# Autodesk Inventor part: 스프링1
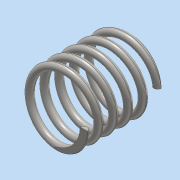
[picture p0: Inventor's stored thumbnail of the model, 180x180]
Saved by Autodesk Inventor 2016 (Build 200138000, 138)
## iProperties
Created: 2019-11
Part Number: 스프링1
Material: 스테인레스 스틸
Document SubType Name: Modeling
Designer: user
Density: 8 g/cm^3
Appearance: 반연마
Mass: 6.56989 g
Surface Area: 16.7192 cm^2
Volume: 0.821237 cm^3
Author: user
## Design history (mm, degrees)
sketch "스케치1"
  geometry: L1 (0, 0)-(8.5, 0); L2 (8.5, 0)-(8.5, -20.5); L3 (8.5, -20.5)-(0, -20.5); L4 (0, -20.5)-(0, 0); C1 r 1 at (8.5, 0)
  constraints: 8 end point, 2 parallel, 1 centre point, 1 coincident, 1 horizontal, 1 perpendicular
  dimensions: "d0" = 17 diameter of L2 L4; "d1" = 20.5 distance between parallel lines of L1 L3 (derived); "d2" = 2 diameter of C1
feature "코일1" sketch "스케치1" pitch "d3" = 10; turns "d5" = 5; dims "d4" = 20.5 (= d1), "d6" = 0, angle "d7" = 90 deg, angle "d8" = 90 deg, "d9" = 0, "d10" = 0
sketch "스케치2"
  geometry: L1 (-20, 0)-(20, 0); L2 (20, 0)-(20, -20.5); L3 (20, -20.5)-(-20, -20.5); L4 (-20, -20.5)-(-20, 0); 2 further points
  constraints: 8 end point, 2 parallel, 1 coincident, 1 horizontal, 1 midpoint, 1 perpendicular
  dimensions: "d11" = 40 distance between parallel lines of L2 L4; "d15" = 20.5 distance between parallel lines of L1 L3 (= d1)
extrude "돌출2" sketch "스케치2" stored distance "d16" = 28.25; taper "d17" = 0 deg
node "솔리드1"
